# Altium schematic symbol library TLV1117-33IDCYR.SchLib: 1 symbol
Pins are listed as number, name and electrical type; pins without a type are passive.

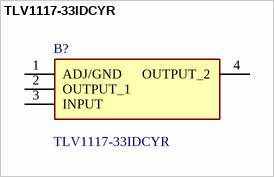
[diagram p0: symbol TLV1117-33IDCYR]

## TLV1117-33IDCYR
designator B?
Single Output LDO, 800mA, Fixed and Adj., Internal Current limit, Thermal Overload Protection; Manufacturer_Name: Texas Instruments; Geometry.Height: 1.8mm
footprint SOT230P700X180-4N
pins: 1 ADJ/GND, 2 OUTPUT_1, 3 INPUT, 4 OUTPUT_2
